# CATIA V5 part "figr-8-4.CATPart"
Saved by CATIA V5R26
Part number: Part1
Bounding box of the stored display mesh (mm): x 4.549 to 89.781, y -52.238 to 26.36, z 54 to 147.773
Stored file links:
  D:\_Deepak\CATIA\CATIA V5-6R2016_Deepak\Resources\Part files\Partfiles\c08_catia_v5_6r2016_prt\figr-8-4.CATPart
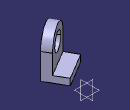
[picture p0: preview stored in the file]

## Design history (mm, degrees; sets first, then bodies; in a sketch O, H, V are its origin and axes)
Body1 (main body)
  Sketch1 on yz-plane, origin (0, 0, 0), H (0, 1, 0), V (0, 0, 1)
    point P1 (-104.4861, 0)
    line L1 (-104.4861, 0) -> (-104.4861, 44.267)
    arc A1 centre (-69.7903, 44.267) radius 34.6958 from (-104.4861, 44.267) to (-35.0946, 44.267) cw
    line L2 (-35.0946, 44.267) -> (-35.0946, 0)
    point P5 (-35.0946, 0)
    line L3 (-35.0946, 0) -> (-104.4861, 0)
    circle A2 centre (-69.7903, 44.267) radius 19.5413
    coincidence: P1 H, P5 H
    vertical: L1 V
    tangency: A1 L1, L2 A1
    horizontal: L3 H
  Pad1: profile Sketch1, direction (1, 0, 0), length 20
  Sketch2 on face of Pad1, origin (0, 0, 0), H (0, -1, 0), V (0, 0, 1)
    point P1 (35.0946, 0)
    line L1 (35.0946, 0) -> (104.4861, 0)
    line L2 (104.4861, 0) -> (104.4861, -15)
    line L3 (104.4861, -15) -> (35.0946, -15)
    line L4 (35.0946, -15) -> (35.0946, 0)
    reference projected line E1 (35.0946, 0) -> (35.0946, 44.267) from edge [face of Pad1 | face of Pad1]
    reference projected line E2 (104.4861, 44.267) -> (104.4861, 0) from edge [face of Pad1 | face of Pad1]
    distance L3 L1 = 15
    coincidence: P1 H, L4 E1, L2 E2
    horizontal: L1 H, L3 H
    vertical: L2 V, L4 V
  Pad2: profile Sketch2, direction (1, 0, 0), length 50
  Translate1: ToTransfor Pad2, Direction xy-plane, Length 69
  Rotate1: ToTransfor Translate1, Axis edge, Angle 121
